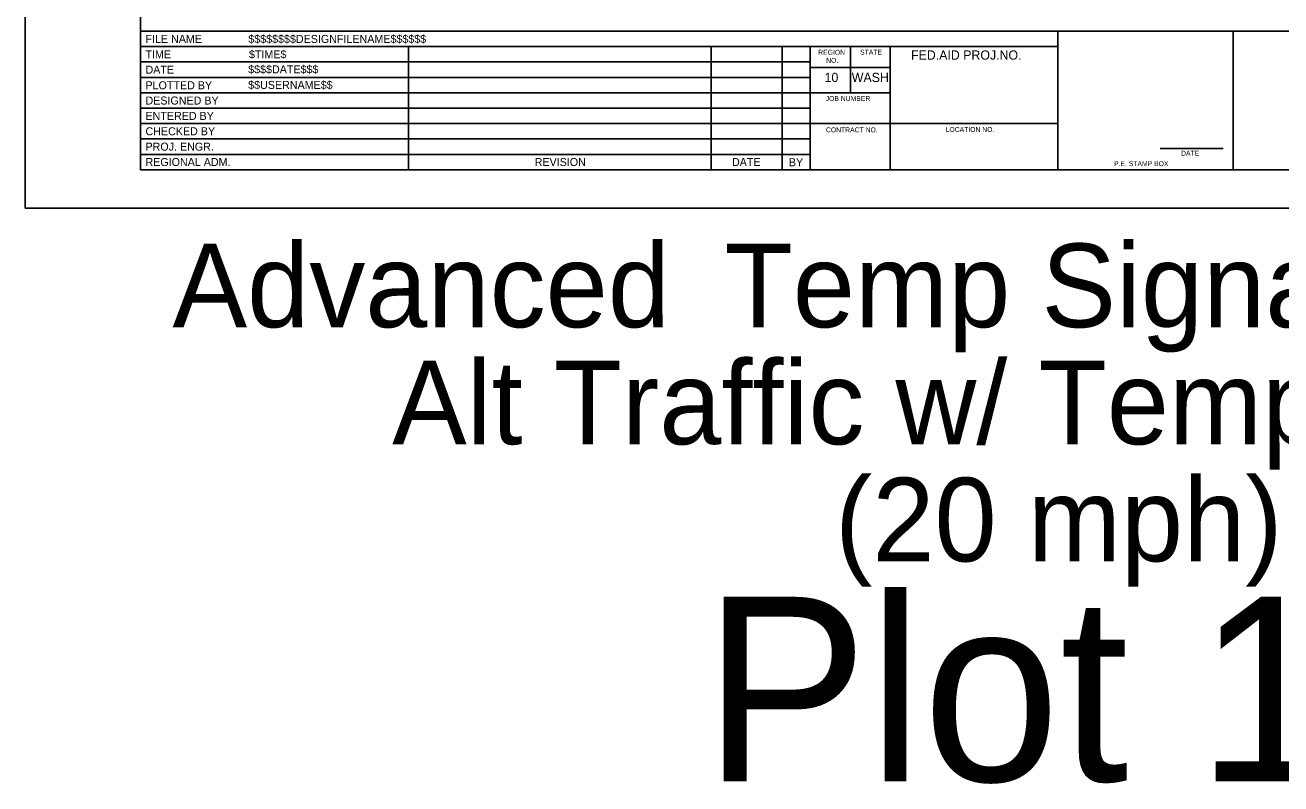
# Model space of a CAD drawing. Extents: x 99982 to 100176, y 99905 to 100011.
# Drawn here: x 99999.06 to 100009.27, y 99965.01 to 99971.18 of the extents above; entities that cross this region are included whole.
import ezdxf

# ---------------------------------------------------------------- set-up
doc = ezdxf.new("R2010")
doc.units = 0
for name, color, linetype in [('SH_GI_PlotLimits', 7, 'Continuous'), ('SH_GI_SheetBorder', 7, 'Continuous'), ('SH_GI_SheetLocationText', 7, 'Continuous'), ('SH_GI_SheetTextInCells', 7, 'Continuous'), ('SH_GI_TitleBlockText', 7, 'Continuous')]:
    doc.layers.add(name, color=color, linetype=linetype)

msp = doc.modelspace()

# ---------------------------------------------------------------- linework, layer by layer
at = {"layer": 'SH_GI_PlotLimits'}
msp.add_lwpolyline([(99999.062, 99969.687), (100016.062, 99969.687), (100016.062, 99980.687), (99999.062, 99980.687)], close=True, dxfattribs=at)
at = {"layer": 'SH_GI_SheetBorder'}
for p, q in [((100000, 99980.375), (100000, 99970)), ((100000, 99971.126), (100015.75, 99971.126)), ((100007.457, 99970), (100007.457, 99971.126)), ((100008.883, 99970), (100008.883, 99971.126)), ((100000, 99971.001), (100007.457, 99971.001)), ((100002.179, 99971.001), (100002.179, 99970)), ((100004.641, 99971.001), (100004.641, 99970)), ((100005.216, 99971.001), (100005.216, 99970)), ((100005.445, 99971.001), (100005.445, 99970)), ((100005.772, 99970.625), (100005.772, 99971.001)), ((100006.096, 99970), (100006.096, 99971.001)), ((100000, 99970.876), (100002.182, 99970.876)), ((100002.182, 99970.876), (100005.447, 99970.876)), ((100006.096, 99970.831), (100005.447, 99970.831)), ((100000, 99970.751), (100002.182, 99970.751)), ((100002.182, 99970.751), (100005.447, 99970.751)), ((100000, 99970.625), (100005.447, 99970.625)), ((100006.096, 99970.625), (100005.447, 99970.625)), ((100000, 99970.5), (100005.447, 99970.5)), ((100000, 99970.375), (100005.447, 99970.375)), ((100007.457, 99970.375), (100005.447, 99970.375)), ((100000, 99970.25), (100005.447, 99970.25)), ((100008.29, 99970.173), (100008.802, 99970.173)), ((100000, 99970.125), (100005.447, 99970.125)), ((100000, 99970), (100015.75, 99970))]:
    msp.add_line(p, q, dxfattribs=at)

# ---------------------------------------------------------------- texts
at = {"layer": 'SH_GI_SheetLocationText'}
for s, height, p in [('Advanced', 0.68, (100000.261, 99968.719)), (' Temp Signal-Controlled', 0.68, (100004.495, 99968.719)), ('Alt Traffic w/ Temp Barrier', 0.68, (100002.046, 99967.767)), (' (20 mph)', 0.68, (100005.394, 99966.815)), ('Plot 11', 1.5, (100004.576, 99965.027))]:
    msp.add_text(s, height=height, dxfattribs=at).set_placement(p)
at = {"layer": 'SH_GI_SheetTextInCells'}
for s, height, p in [('FILE NAME', 0.0651, (100000.041, 99971.031)), ('REGION', 0.04, (100005.51, 99970.935)), ('STATE', 0.04, (100005.851, 99970.936)), ('TIME', 0.0651, (100000.041, 99970.906)), ('NO.', 0.04, (100005.575, 99970.869)), ('FED.AID PROJ.NO.', 0.07506, (100006.265, 99970.895)), ('DATE', 0.0651, (100000.041, 99970.781)), ('10', 0.0751, (100005.562, 99970.713)), ('WASH', 0.0751, (100005.783, 99970.713)), ('PLOTTED BY', 0.0651, (100000.041, 99970.654)), ('DESIGNED BY', 0.06505, (100000.041, 99970.53)), ('JOB NUMBER', 0.04, (100005.571, 99970.559)), ('ENTERED BY', 0.0651, (100000.041, 99970.405)), ('CHECKED BY', 0.0651, (100000.041, 99970.28)), ('CONTRACT NO.', 0.04003, (100005.573, 99970.304)), ('LOCATION NO.', 0.04003, (100006.546, 99970.307)), ('PROJ. ENGR.', 0.06505, (100000.041, 99970.155)), ('REGIONAL ADM.', 0.06505, (100000.041, 99970.03)), ('REVISION', 0.0651, (100003.205, 99970.03)), ('DATE', 0.0651, (100004.809, 99970.03)), ('BY', 0.0651, (100005.272, 99970.028)), ('P.E. STAMP BOX', 0.04003, (100007.915, 99970.029)), ('DATE', 0.04, (100008.46, 99970.114))]:
    msp.add_text(s, height=height, dxfattribs=at).set_placement(p)
at = {"layer": 'SH_GI_TitleBlockText'}
for s, height, p in [('$$$$$$$$DESIGNFILENAME$$$$$$', 0.06505, (100000.877, 99971.031)), ('$TIME$', 0.0651, (100000.882, 99970.906)), ('$$$$DATE$$$', 0.06505, (100000.876, 99970.784)), ('$$USERNAME$$', 0.06505, (100000.876, 99970.657))]:
    msp.add_text(s, height=height, dxfattribs=at).set_placement(p)

doc.saveas('drawing.dxf')
